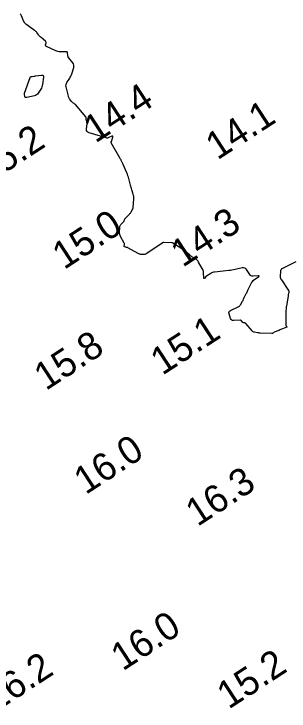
# Model space of a CAD drawing. Extents: x 1023796 to 1112670, y 656573 to 837340.
# Drawn here: x 1102146 to 1102195.9, y 687135.9 to 687262.5 of the extents above; entities that cross this region are included whole.
import ezdxf

# ---------------------------------------------------------------- set-up
doc = ezdxf.new("R2010")
doc.units = 0
doc.layers.add('V-CHAN-CONT-15FT', color=7, linetype='Continuous')
doc.layers.add('V-TOPO-SOUN', color=7, linetype='Continuous')

msp = doc.modelspace()

# ---------------------------------------------------------------- linework, layer by layer
at = {"layer": 'V-CHAN-CONT-15FT'}
msp.add_lwpolyline([(1102197.16, 687217.49), (1102194.74, 687216.29), (1102194.59, 687216.19), (1102194.47, 687216.05), (1102194.4, 687215.9), (1102194.37, 687215.71), (1102194.34, 687214.91), (1102194.34, 687214.71), (1102194.38, 687214.52), (1102194.45, 687214.35), (1102194.55, 687214.18), (1102195.85, 687212.29), (1102195.89, 687212.22), (1102195.91, 687212.14), (1102195.92, 687212.06), (1102195.9, 687211.98), (1102195.81, 687211.64), (1102195.79, 687211.56), (1102195.77, 687211.47), (1102195.76, 687211.39), (1102195.74, 687211.3), (1102195.44, 687209.42), (1102195.42, 687209.31), (1102195.41, 687209.2), (1102195.4, 687209.08), (1102195.39, 687208.97), (1102195.36, 687208.51), (1102195.36, 687208.39), (1102195.35, 687208.28), (1102195.35, 687208.17), (1102195.35, 687208.05), (1102195.37, 687205.93), (1102195.37, 687205.89), (1102195.38, 687205.86), (1102195.4, 687205.83), (1102195.43, 687205.8), (1102195.55, 687205.71), (1102195.57, 687205.69), (1102195.58, 687205.67), (1102195.56, 687205.65), (1102195.54, 687205.63), (1102194.27, 687205.11), (1102194.25, 687205.1), (1102194.23, 687205.1), (1102194.22, 687205.09), (1102194.2, 687205.08), (1102194.13, 687205.05), (1102194.11, 687205.05), (1102194.1, 687205.04), (1102194.08, 687205.03), (1102194.06, 687205.03), (1102193.26, 687204.7), (1102193.22, 687204.68), (1102193.18, 687204.66), (1102193.14, 687204.63), (1102193.1, 687204.6), (1102192.96, 687204.49), (1102192.92, 687204.46), (1102192.88, 687204.45), (1102192.84, 687204.44), (1102192.79, 687204.43), (1102190.71, 687204.53), (1102190.58, 687204.54), (1102190.44, 687204.55), (1102190.31, 687204.57), (1102190.18, 687204.59), (1102189.66, 687204.67), (1102189.53, 687204.7), (1102189.42, 687204.75), (1102189.31, 687204.82), (1102189.22, 687204.92), (1102188.09, 687206.28), (1102188.05, 687206.31), (1102188.02, 687206.34), (1102187.97, 687206.36), (1102187.93, 687206.37), (1102187.73, 687206.39), (1102187.68, 687206.4), (1102187.64, 687206.42), (1102187.6, 687206.44), (1102187.56, 687206.48), (1102187.31, 687206.75), (1102187.25, 687206.8), (1102187.18, 687206.84), (1102187.11, 687206.86), (1102187.04, 687206.86), (1102185.89, 687206.79), (1102185.69, 687206.81), (1102185.53, 687206.88), (1102185.4, 687207), (1102185.32, 687207.18), (1102185.05, 687208.03), (1102185.02, 687208.23), (1102185.05, 687208.4), (1102185.15, 687208.53), (1102185.32, 687208.64), (1102186.7, 687209.3), (1102186.82, 687209.37), (1102186.94, 687209.45), (1102187.03, 687209.55), (1102187.11, 687209.67), (1102187.5, 687210.32), (1102187.53, 687210.37), (1102187.56, 687210.42), (1102187.58, 687210.48), (1102187.6, 687210.53), (1102187.68, 687210.76), (1102187.7, 687210.81), (1102187.72, 687210.87), (1102187.75, 687210.92), (1102187.78, 687210.97), (1102188.17, 687211.72), (1102188.25, 687211.87), (1102188.32, 687212.01), (1102188.4, 687212.15), (1102188.47, 687212.3), (1102189.2, 687213.77), (1102189.22, 687213.81), (1102189.24, 687213.85), (1102189.27, 687213.89), (1102189.3, 687213.92), (1102189.42, 687214.06), (1102189.46, 687214.1), (1102189.49, 687214.13), (1102189.53, 687214.16), (1102189.57, 687214.19), (1102190.39, 687214.74), (1102190.5, 687214.83), (1102190.52, 687214.89), (1102190.47, 687214.92), (1102190.33, 687214.92), (1102189.44, 687214.85), (1102189.24, 687214.86), (1102189.07, 687214.92), (1102188.92, 687215.02), (1102188.79, 687215.17), (1102188.21, 687216.06), (1102188.06, 687216.23), (1102187.88, 687216.34), (1102187.68, 687216.39), (1102187.45, 687216.37), (1102186.17, 687216.08), (1102185.87, 687216.02), (1102185.58, 687215.96), (1102185.28, 687215.92), (1102184.98, 687215.88), (1102182.39, 687215.6), (1102182.21, 687215.57), (1102182.05, 687215.53), (1102181.89, 687215.46), (1102181.74, 687215.37), (1102180.95, 687214.86), (1102180.9, 687214.83), (1102180.85, 687214.78), (1102180.8, 687214.73), (1102180.76, 687214.68), (1102180.59, 687214.47), (1102180.55, 687214.43), (1102180.52, 687214.42), (1102180.5, 687214.44), (1102180.49, 687214.5), (1102180.42, 687215.53), (1102180.39, 687215.73), (1102180.35, 687215.91), (1102180.28, 687216.09), (1102180.19, 687216.27), (1102179.53, 687217.44), (1102179.44, 687217.59), (1102179.33, 687217.72), (1102179.2, 687217.83), (1102179.06, 687217.93), (1102178.42, 687218.3), (1102178.29, 687218.39), (1102178.16, 687218.48), (1102178.03, 687218.58), (1102177.92, 687218.69), (1102177.46, 687219.13), (1102177.34, 687219.24), (1102177.22, 687219.34), (1102177.09, 687219.43), (1102176.96, 687219.52), (1102174.82, 687220.89), (1102174.81, 687220.89), (1102174.8, 687220.9), (1102174.79, 687220.9), (1102174.78, 687220.9), (1102174.73, 687220.9), (1102174.72, 687220.9), (1102174.7, 687220.9), (1102174.69, 687220.9), (1102174.68, 687220.9), (1102173.19, 687220.98), (1102173.17, 687220.98), (1102173.15, 687220.98), (1102173.12, 687220.98), (1102173.1, 687220.97), (1102173.01, 687220.94), (1102172.99, 687220.93), (1102172.96, 687220.92), (1102172.94, 687220.91), (1102172.92, 687220.89), (1102170.1, 687218.96), (1102169.99, 687218.9), (1102169.87, 687218.85), (1102169.74, 687218.82), (1102169.61, 687218.82), (1102169.06, 687218.83), (1102168.93, 687218.84), (1102168.8, 687218.87), (1102168.67, 687218.91), (1102168.55, 687218.97), (1102166.71, 687220.01), (1102166.68, 687220.03), (1102166.65, 687220.04), (1102166.61, 687220.05), (1102166.58, 687220.05), (1102166.45, 687220.07), (1102166.42, 687220.08), (1102166.38, 687220.09), (1102166.35, 687220.1), (1102166.32, 687220.11), (1102166.07, 687220.18), (1102166.03, 687220.2), (1102166, 687220.23), (1102165.99, 687220.27), (1102165.99, 687220.32), (1102166.07, 687220.63), (1102166.08, 687220.69), (1102166.07, 687220.76), (1102166.06, 687220.82), (1102166.03, 687220.89), (1102165.35, 687222.09), (1102165.27, 687222.27), (1102165.21, 687222.46), (1102165.18, 687222.65), (1102165.18, 687222.85), (1102165.22, 687223.79), (1102165.24, 687223.93), (1102165.28, 687224.05), (1102165.34, 687224.16), (1102165.43, 687224.26), (1102165.92, 687224.76), (1102165.96, 687224.81), (1102166, 687224.86), (1102166.02, 687224.91), (1102166.04, 687224.96), (1102166.12, 687225.2), (1102166.14, 687225.26), (1102166.16, 687225.31), (1102166.2, 687225.36), (1102166.24, 687225.4), (1102166.98, 687226.15), (1102167.06, 687226.24), (1102167.14, 687226.34), (1102167.22, 687226.45), (1102167.28, 687226.56), (1102167.65, 687227.22), (1102167.66, 687227.23), (1102167.66, 687227.24), (1102167.66, 687227.25), (1102167.66, 687227.26), (1102167.67, 687227.3), (1102167.67, 687227.32), (1102167.67, 687227.34), (1102167.77, 687228.89), (1102167.77, 687229.11), (1102167.76, 687229.32), (1102167.72, 687229.53), (1102167.67, 687229.74), (1102167.42, 687230.57), (1102167.36, 687230.78), (1102167.3, 687230.99), (1102167.24, 687231.2), (1102167.18, 687231.4), (1102166.86, 687232.59), (1102166.78, 687232.86), (1102166.69, 687233.12), (1102166.6, 687233.38), (1102166.49, 687233.63), (1102165.84, 687235.17), (1102165.8, 687235.26), (1102165.76, 687235.35), (1102165.72, 687235.44), (1102165.68, 687235.53), (1102165.5, 687235.89), (1102165.46, 687235.98), (1102165.41, 687236.07), (1102165.37, 687236.15), (1102165.32, 687236.24), (1102163.64, 687239.08), (1102163.63, 687239.1), (1102163.62, 687239.12), (1102163.63, 687239.14), (1102163.63, 687239.16), (1102163.67, 687239.26), (1102163.67, 687239.28), (1102163.68, 687239.3), (1102163.69, 687239.32), (1102163.7, 687239.35), (1102163.94, 687240.12), (1102163.96, 687240.23), (1102163.94, 687240.3), (1102163.88, 687240.31), (1102163.77, 687240.27), (1102163.26, 687240.03), (1102163.13, 687239.98), (1102163, 687239.96), (1102162.87, 687239.96), (1102162.73, 687239.99), (1102159.64, 687240.92), (1102159.43, 687241.02), (1102159.28, 687241.16), (1102159.21, 687241.35), (1102159.2, 687241.59), (1102159.36, 687243.07), (1102159.36, 687243.1), (1102159.35, 687243.12), (1102159.34, 687243.13), (1102159.31, 687243.14), (1102159.19, 687243.16), (1102159.17, 687243.17), (1102159.15, 687243.18), (1102159.14, 687243.21), (1102159.13, 687243.23), (1102159.12, 687243.56), (1102159.12, 687243.62), (1102159.1, 687243.68), (1102159.07, 687243.73), (1102159.04, 687243.79), (1102157.18, 687246.03), (1102157.13, 687246.08), (1102157.07, 687246.13), (1102157.02, 687246.18), (1102156.95, 687246.22), (1102156.7, 687246.38), (1102156.64, 687246.42), (1102156.58, 687246.46), (1102156.53, 687246.52), (1102156.49, 687246.57), (1102156.11, 687247.09), (1102156.04, 687247.2), (1102155.98, 687247.32), (1102155.93, 687247.44), (1102155.89, 687247.56), (1102155.49, 687249.23), (1102155.46, 687249.45), (1102155.47, 687249.66), (1102155.53, 687249.86), (1102155.63, 687250.05), (1102156.14, 687250.82), (1102156.25, 687251.01), (1102156.36, 687251.22), (1102156.45, 687251.42), (1102156.52, 687251.64), (1102156.87, 687252.78), (1102156.91, 687253.01), (1102156.9, 687253.22), (1102156.83, 687253.42), (1102156.71, 687253.62), (1102155.94, 687254.56), (1102155.88, 687254.65), (1102155.83, 687254.75), (1102155.8, 687254.85), (1102155.78, 687254.96), (1102155.75, 687255.42), (1102155.73, 687255.52), (1102155.68, 687255.59), (1102155.61, 687255.63), (1102155.51, 687255.64), (1102154.43, 687255.61), (1102154.22, 687255.62), (1102154.01, 687255.65), (1102153.8, 687255.71), (1102153.6, 687255.79), (1102151.91, 687256.58), (1102151.83, 687256.63), (1102151.78, 687256.69), (1102151.76, 687256.76), (1102151.77, 687256.86), (1102151.84, 687257.25), (1102151.84, 687257.34), (1102151.83, 687257.42), (1102151.78, 687257.5), (1102151.72, 687257.57), (1102150.93, 687258.22), (1102150.82, 687258.32), (1102150.71, 687258.42), (1102150.62, 687258.53), (1102150.53, 687258.64), (1102150.18, 687259.11), (1102150.09, 687259.23), (1102149.99, 687259.33), (1102149.88, 687259.43), (1102149.76, 687259.52), (1102148.37, 687260.51), (1102148.18, 687260.67), (1102148.02, 687260.85), (1102147.88, 687261.04), (1102147.77, 687261.26), (1102147.39, 687262.18), (1102147.27, 687262.38), (1102147.12, 687262.54)], dxfattribs=at)
msp.add_lwpolyline([(1102150.14, 687247.81), (1102149.96, 687247.71), (1102149.76, 687247.64), (1102148.36, 687247.33), (1102148.33, 687247.33), (1102148.3, 687247.32), (1102148.26, 687247.32), (1102148.23, 687247.32), (1102148.05, 687247.34), (1102148.04, 687247.34), (1102148.03, 687247.35), (1102148.03, 687247.36), (1102148.03, 687247.37), (1102148.02, 687247.43), (1102148.02, 687247.44), (1102148.02, 687247.46), (1102148.02, 687247.47), (1102148.02, 687247.48), (1102147.93, 687247.86), (1102147.92, 687247.93), (1102147.92, 687247.99), (1102147.92, 687248.06), (1102147.94, 687248.12), (1102148.94, 687250.97), (1102148.96, 687251), (1102148.98, 687251.03), (1102149, 687251.05), (1102149.03, 687251.07), (1102149.17, 687251.13), (1102149.2, 687251.14), (1102149.23, 687251.15), (1102149.27, 687251.16), (1102149.3, 687251.16), (1102149.64, 687251.2), (1102149.71, 687251.2), (1102149.77, 687251.21), (1102149.84, 687251.22), (1102149.91, 687251.23), (1102151.01, 687251.39), (1102151.18, 687251.39), (1102151.3, 687251.33), (1102151.36, 687251.21), (1102151.36, 687251.04), (1102151.18, 687249.66), (1102151.14, 687249.44), (1102151.08, 687249.24), (1102150.99, 687249.04), (1102150.89, 687248.85), (1102150.42, 687248.11), (1102150.29, 687247.94)], close=True, dxfattribs=at)

# ---------------------------------------------------------------- texts
at = {"layer": 'V-TOPO-SOUN'}
for s, p in [('14.4 ', (1102160.8, 687238.94)), ('14.1 ', (1102182.94, 687235.87)), ('15.2 ', (1102141.12, 687231.43)), ('15.0 ', (1102155.12, 687215.96)), ('14.3 ', (1102176.62, 687216.37)), ('15.1 ', (1102172.94, 687196.76)), ('15.8 ', (1102151.81, 687193.99)), ('16.0 ', (1102159.03, 687175.09)), ('16.3 ', (1102179.31, 687169.29)), ('16.0 ', (1102165.75, 687143.06)), ('16.2 ', (1102142.63, 687135.6)), ('15.2 ', (1102184.98, 687136.12))]:
    msp.add_text(s, height=5, rotation=33.0949, dxfattribs=at).set_placement(p)

doc.saveas('drawing.dxf')
